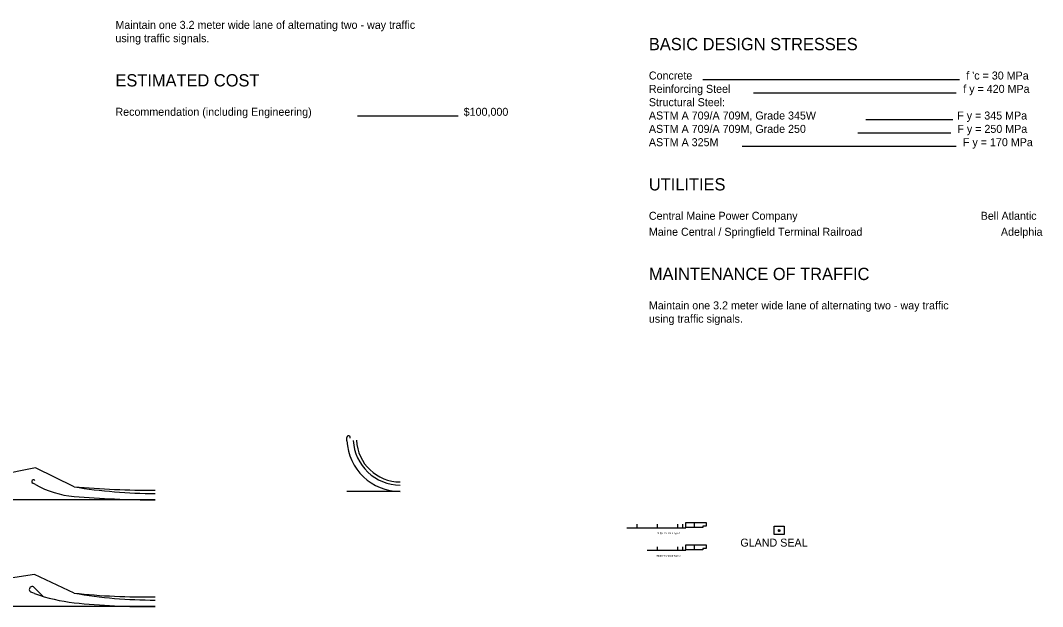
# Model space of a CAD drawing. Extents: x 604404 to 604584, y 419490 to 419604.
# Drawn here: x 604487.3 to 604583.1, y 419489.5 to 419544.5 of the extents above; entities that cross this region are included whole.
import ezdxf

# ---------------------------------------------------------------- set-up
doc = ezdxf.new("R2010")
doc.units = 0
for name, color, linetype in [('Level 17', 7, 'Continuous'), ('Level 18', 7, 'Continuous'), ('Level 19', 7, 'Continuous'), ('Level 20', 7, 'Continuous'), ('Level 21', 7, 'Continuous'), ('Level 27', 7, 'Continuous'), ('Level 28', 7, 'Continuous'), ('Level 50', 7, 'Continuous'), ('Level 51', 7, 'Continuous')]:
    doc.layers.add(name, color=color, linetype=linetype)

msp = doc.modelspace()

# ---------------------------------------------------------------- linework, layer by layer
at = {"layer": 'Level 17'}
for p, q in [((604488.722, 419502.516), (604473.719, 419499.516)), ((604492.337, 419500.741), (604488.722, 419502.516)), ((604550.478, 419496.919), (604550.478, 419497.394)), ((604550.478, 419494.82), (604550.478, 419495.295)), ((604488.638, 419492.516), (604468.638, 419489.516)), ((604492.34, 419490.771), (604488.638, 419492.516))]:
    msp.add_line(p, q, dxfattribs=at)
for points in [[(604551.278, 419496.919), (604549.678, 419496.919), (604549.678, 419497.394), (604551.578, 419497.394), (604551.578, 419497.049), (604551.278, 419497.049), (604551.278, 419496.919)], [(604551.278, 419494.82), (604549.678, 419494.82), (604549.678, 419495.295), (604551.578, 419495.295), (604551.578, 419494.95), (604551.278, 419494.95), (604551.278, 419494.82)]]:
    msp.add_lwpolyline(points, dxfattribs=at)
for centre, radius, start, end in [((604522.907, 419505.298), 4.4, 182.68063, 270.00009), ((604522.907, 419505.298), 4.1, 182.68063, 270.00009), ((604499.947, 419589.674), 89.258, 265.10911, 270), ((604499.947, 419546.759), 46.642, 260.60981, 270), ((604499.141, 419554.827), 64.416, 263.93933, 267.32786), ((604499.947, 419534.617), 44.5, 260.15738, 270), ((604499.141, 419554.827), 64.416, 267.32786, 270.71684)]:
    msp.add_arc(centre, radius, start, end, dxfattribs=at)
at = {"layer": 'Level 18'}
for p, q in [((604517.913, 419505.065), (604517.899, 419505.362)), ((604488.719, 419500.943), (604488.458, 419501.088)), ((604488.638, 419490.736), (604488.319, 419490.854)), ((604489.443, 419490.465), (604488.606, 419491.303))]:
    msp.add_line(p, q, dxfattribs=at)
for centre, radius, start, end in [((604518.061, 419505.37), 0.163, 336.2087, 182.6597), ((604522.907, 419505.298), 5, 182.68063, 270), ((604488.538, 419501.231), 0.163, 34.42209, 240.87309), ((604493.097, 419508.807), 9, 240.89401, 265.14953), ((604499.947, 419589.516), 90, 265.14894, 270), ((604488.413, 419491.11), 0.273, 44.93167, 249.75607), ((604493.965, 419505.184), 15.398, 249.7574, 263.93933), ((604499.141, 419553.927), 64.416, 263.93933, 267.32786), ((604499.141, 419553.927), 64.416, 267.32786, 270.71684)]:
    msp.add_arc(centre, radius, start, end, dxfattribs=at)
at = {"layer": 'Level 19'}
for p, q in [((604558.292, 419496.654), (604558.394, 419496.654)), ((604558.365, 419496.645), (604558.302, 419496.645)), ((604558.378, 419496.669), (604558.378, 419496.694)), ((604558.378, 419496.687), (604558.378, 419496.694)), ((604558.378, 419496.669), (604558.378, 419496.675)), ((604558.385, 419496.562), (604558.385, 419496.625)), ((604558.386, 419496.694), (604558.386, 419496.691)), ((604558.386, 419496.671), (604558.386, 419496.669)), ((604558.386, 419496.671), (604558.386, 419496.669)), ((604558.387, 419496.689), (604558.398, 419496.682)), ((604558.392, 419496.692), (604558.399, 419496.7)), ((604558.393, 419496.656), (604558.393, 419496.671)), ((604558.393, 419496.669), (604558.393, 419496.671)), ((604558.402, 419496.661), (604558.394, 419496.666)), ((604558.394, 419496.654), (604558.394, 419496.552)), ((604558.401, 419496.675), (604558.401, 419496.673)), ((604558.405, 419496.667), (604558.406, 419496.666)), ((604558.444, 419496.667), (604558.443, 419496.666)), ((604558.447, 419496.661), (604558.455, 419496.666)), ((604558.448, 419496.675), (604558.448, 419496.673)), ((604558.457, 419496.692), (604558.45, 419496.7)), ((604558.462, 419496.689), (604558.451, 419496.682)), ((604558.454, 419496.654), (604558.454, 419496.552)), ((604558.556, 419496.654), (604558.454, 419496.654)), ((604558.456, 419496.656), (604558.456, 419496.671)), ((604558.456, 419496.669), (604558.456, 419496.671)), ((604558.463, 419496.694), (604558.463, 419496.691)), ((604558.463, 419496.671), (604558.463, 419496.669)), ((604558.463, 419496.671), (604558.463, 419496.669)), ((604558.464, 419496.562), (604558.464, 419496.625)), ((604558.471, 419496.669), (604558.471, 419496.694)), ((604558.471, 419496.687), (604558.471, 419496.694)), ((604558.471, 419496.669), (604558.471, 419496.675)), ((604558.483, 419496.645), (604558.547, 419496.645))]:
    msp.add_line(p, q, dxfattribs=at)
for points in [[(604558.399, 419496.702), (604558.393, 419496.708), (604558.372, 419496.708), (604558.366, 419496.702), (604558.366, 419496.661), (604558.372, 419496.654), (604558.391, 419496.654)], [(604558.45, 419496.702), (604558.456, 419496.708), (604558.476, 419496.708), (604558.483, 419496.702), (604558.483, 419496.661), (604558.476, 419496.654), (604558.458, 419496.654)]]:
    msp.add_lwpolyline(points, dxfattribs=at)
for centre, radius, start, end in [((604558.302, 419496.654), 0.0095, 180, 270), ((604558.365, 419496.625), 0.0195, 0, 90), ((604558.382, 419496.694), 0.00422, 6.06579, 180), ((604558.382, 419496.694), 0.00422, 0, 180), ((604558.374, 419496.681), 0.00675, 300, 60), ((604558.382, 419496.669), 0.00422, 180, 0), ((604558.382, 419496.669), 0.00422, 180, 0), ((604558.394, 419496.562), 0.0095, 180, 270), ((604558.389, 419496.695), 0.00337, 186.07126, 315.00547), ((604558.388, 419496.691), 0.00169, 180, 236.30993), ((604558.389, 419496.671), 0.00337, 0, 180), ((604558.389, 419496.671), 0.00337, 0, 180), ((604558.391, 419496.656), 0.00169, 270, 0), ((604558.396, 419496.669), 0.00337, 180, 233.5525), ((604558.393, 419496.675), 0.00796, 0, 56.30993), ((604558.398, 419496.701), 0.00169, 315, 45), ((604558.405, 419496.673), 0.00435, 180, 211.60414), ((604558.414, 419496.678), 0.0145, 211.60414, 228.73675), ((604558.384, 419496.637), 0.0296, 31.29763, 53.5525), ((604558.384, 419496.637), 0.0364, 31.29763, 53.5525), ((604558.358, 419496.621), 0.06, 18.73675, 31.29763), ((604558.358, 419496.621), 0.0668, 18.73675, 31.29763), ((604558.409, 419496.625), 0.00868, 0.76049, 15.51312), ((604558.427, 419496.625), 0.0101, 180.76049, 205.08357), ((604558.424, 419496.623), 0.0061, 205.08357, 243.73675), ((604558.424, 419496.625), 0.00756, 243.73675, 269.84716), ((604558.409, 419496.625), 0.0155, 0.76049, 15.24409), ((604558.427, 419496.625), 0.00329, 180.76049, 205.08357), ((604558.421, 419496.625), 0.00329, 334.91643, 359.23951), ((604558.424, 419496.625), 0.00756, 270.15284, 296.26325), ((604558.44, 419496.625), 0.0155, 164.75591, 179.23951), ((604558.491, 419496.621), 0.0668, 148.70237, 161.26325), ((604558.425, 419496.623), 0.0061, 296.26325, 334.91643), ((604558.421, 419496.625), 0.0101, 334.91643, 359.23951), ((604558.44, 419496.625), 0.00868, 164.48688, 179.23951), ((604558.465, 419496.637), 0.0364, 126.4475, 148.70237), ((604558.491, 419496.621), 0.06, 148.70237, 161.26325), ((604558.465, 419496.637), 0.0296, 126.4475, 148.70237), ((604558.435, 419496.678), 0.0145, 311.26325, 328.39586), ((604558.443, 419496.673), 0.00435, 328.39586, 0), ((604558.456, 419496.675), 0.00796, 123.69007, 180), ((604558.451, 419496.701), 0.00169, 135, 225), ((604558.454, 419496.562), 0.0095, 270, 0), ((604558.453, 419496.669), 0.00337, 306.4475, 360), ((604558.46, 419496.671), 0.00337, 0, 180), ((604558.46, 419496.671), 0.00337, 0, 180), ((604558.458, 419496.656), 0.00169, 180, 270), ((604558.46, 419496.695), 0.00337, 224.99453, 353.92874), ((604558.461, 419496.691), 0.00169, 303.69007, 360), ((604558.467, 419496.694), 0.00422, 360, 173.93421), ((604558.467, 419496.694), 0.00422, 0, 180), ((604558.467, 419496.669), 0.00422, 180, 0), ((604558.467, 419496.669), 0.00422, 180, 0), ((604558.483, 419496.625), 0.0195, 90, 180), ((604558.475, 419496.681), 0.00675, 120, 240), ((604558.547, 419496.654), 0.0095, 270, 0)]:
    msp.add_arc(centre, radius, start, end, dxfattribs=at)
for centre, major_axis, ratio, start_param, end_param in [((604558.294, 419496.561), (0, 0.248), 0.515887, 4.983144, 5.039407), ((604558.294, 419496.561), (0, 0.255), 0.528815, 4.982856, 5.039407), ((604558.555, 419496.561), (0, -0.255), 0.528815, 4.385371, 4.441922), ((604558.555, 419496.561), (0, -0.248), 0.515887, 4.385371, 4.441634)]:
    msp.add_ellipse(centre, major_axis=major_axis, ratio=ratio, start_param=start_param, end_param=end_param, dxfattribs=at)
at = {"layer": 'Level 20'}
for p, q in [((604551.26, 419538.924), (604575.335, 419538.924)), ((604556.034, 419537.674), (604575.026, 419537.674)), ((604518.907, 419535.524), (604528.351, 419535.524)), ((604566.543, 419535.174), (604574.717, 419535.174)), ((604565.787, 419533.924), (604574.511, 419533.924)), ((604554.969, 419532.674), (604575.026, 419532.674))]:
    msp.add_line(p, q, dxfattribs=at)
at = {"layer": 'Level 21'}
for p, q in [((604545.041, 419497.194), (604545.141, 419497.194)), ((604545.091, 419497.194), (604545.091, 419496.894)), ((604546.946, 419497.194), (604547.046, 419497.194)), ((604546.996, 419497.194), (604546.996, 419496.894)), ((604548.851, 419497.194), (604548.951, 419497.194)), ((604548.901, 419497.194), (604548.901, 419496.894)), ((604549.327, 419497.194), (604549.427, 419497.194)), ((604549.377, 419497.194), (604549.377, 419496.894)), ((604544.139, 419496.894), (604549.678, 419496.894)), ((604545.041, 419497.044), (604545.141, 419497.044)), ((604546.946, 419497.044), (604547.046, 419497.044)), ((604548.851, 419497.044), (604548.951, 419497.044)), ((604549.327, 419497.044), (604549.427, 419497.044)), ((604546.044, 419494.795), (604549.678, 419494.795)), ((604546.946, 419495.095), (604547.046, 419495.095)), ((604546.946, 419494.945), (604547.046, 419494.945)), ((604546.996, 419495.095), (604546.996, 419494.795)), ((604548.851, 419495.095), (604548.951, 419495.095)), ((604548.851, 419494.945), (604548.951, 419494.945)), ((604548.901, 419495.095), (604548.901, 419494.795)), ((604549.327, 419495.095), (604549.427, 419495.095)), ((604549.327, 419494.945), (604549.427, 419494.945)), ((604549.377, 419495.095), (604549.377, 419494.795))]:
    msp.add_line(p, q, dxfattribs=at)
at = {"layer": 'Level 27'}
msp.add_lwpolyline([(604558.89, 419496.256), (604557.959, 419496.256), (604557.959, 419497.053), (604558.89, 419497.053)], close=True, dxfattribs=at)
at = {"layer": 'Level 28'}
for p, q in [((604558.393, 419496.708), (604558.456, 419496.708)), ((604558.424, 419496.507), (604558.424, 419496.708))]:
    msp.add_line(p, q, dxfattribs=at)
at = {"layer": 'Level 50'}
for p, q in [((604522.907, 419500.298), (604517.913, 419500.298)), ((604499.947, 419499.516), (604473.719, 419499.516)), ((604499.947, 419489.516), (604468.638, 419489.516))]:
    msp.add_line(p, q, dxfattribs=at)
at = {"layer": 'Level 51'}
for p, q in [((604558.378, 419496.694), (604558.378, 419496.687)), ((604558.378, 419496.675), (604558.378, 419496.669)), ((604558.386, 419496.691), (604558.386, 419496.694)), ((604558.386, 419496.669), (604558.386, 419496.671)), ((604558.398, 419496.682), (604558.387, 419496.689)), ((604558.393, 419496.671), (604558.393, 419496.669)), ((604558.394, 419496.666), (604558.402, 419496.661)), ((604558.401, 419496.673), (604558.401, 419496.675)), ((604558.406, 419496.666), (604558.405, 419496.667)), ((604558.444, 419496.667), (604558.443, 419496.666)), ((604558.447, 419496.661), (604558.455, 419496.666)), ((604558.448, 419496.675), (604558.448, 419496.673)), ((604558.462, 419496.689), (604558.451, 419496.682)), ((604558.456, 419496.669), (604558.456, 419496.671)), ((604558.463, 419496.694), (604558.463, 419496.691)), ((604558.463, 419496.671), (604558.463, 419496.669)), ((604558.471, 419496.687), (604558.471, 419496.694)), ((604558.471, 419496.669), (604558.471, 419496.675))]:
    msp.add_line(p, q, dxfattribs=at)
for centre, radius, start, end in [((604558.382, 419496.694), 0.00422, 0.0004, 180), ((604558.374, 419496.681), 0.00675, 300, 60), ((604558.382, 419496.669), 0.00422, 180.00012, 0), ((604558.389, 419496.671), 0.00337, 360, 179.99989), ((604558.396, 419496.669), 0.00337, 180.00045, 233.5525), ((604558.393, 419496.675), 0.00796, 0, 56.30993), ((604558.405, 419496.673), 0.00435, 180, 211.58373), ((604558.414, 419496.678), 0.0145, 211.60414, 228.73633), ((604558.384, 419496.637), 0.0296, 31.29763, 53.55248), ((604558.384, 419496.637), 0.0364, 31.29763, 52.34679), ((604558.358, 419496.621), 0.06, 18.73675, 31.2919), ((604558.358, 419496.621), 0.0668, 18.73675, 31.29763), ((604558.409, 419496.625), 0.00868, 0.76049, 15.51309), ((604558.427, 419496.625), 0.0101, 180.7605, 205.08357), ((604558.424, 419496.623), 0.0061, 205.08379, 243.73675), ((604558.424, 419496.625), 0.00756, 243.73675, 269.84716), ((604558.424, 419496.625), 0.00756, 270.15284, 296.26325), ((604558.491, 419496.621), 0.0668, 148.70237, 161.26325), ((604558.425, 419496.623), 0.0061, 296.26325, 334.91643), ((604558.421, 419496.625), 0.0101, 334.91643, 359.23951), ((604558.44, 419496.625), 0.00868, 164.48688, 179.23951), ((604558.465, 419496.637), 0.0364, 127.65321, 148.70237), ((604558.491, 419496.621), 0.06, 148.70237, 161.26325), ((604558.465, 419496.637), 0.0296, 126.4475, 148.70237), ((604558.435, 419496.678), 0.0145, 311.26325, 328.39586), ((604558.443, 419496.673), 0.00435, 328.39586, 0), ((604558.456, 419496.675), 0.00796, 123.69007, 180), ((604558.453, 419496.669), 0.00337, 306.4475, 360), ((604558.46, 419496.671), 0.00337, 0, 180), ((604558.467, 419496.694), 0.00422, 0, 180), ((604558.467, 419496.669), 0.00422, 180, 0), ((604558.475, 419496.681), 0.00675, 120, 240)]:
    msp.add_arc(centre, radius, start, end, dxfattribs=at)
for centre, major_axis, ratio, start_param, end_param in [((604558.294, 419496.561), (0, 0.248), 0.515887, 4.983144, 5.039407), ((604558.294, 419496.561), (0, 0.255), 0.528815, 4.982856, 5.039407), ((604558.555, 419496.561), (0, -0.255), 0.528815, 4.385371, 4.441922), ((604558.555, 419496.561), (0, -0.248), 0.515887, 4.385371, 4.441634)]:
    msp.add_ellipse(centre, major_axis=major_axis, ratio=ratio, start_param=start_param, end_param=end_param, dxfattribs=at)

# ---------------------------------------------------------------- texts
at = {"layer": 'Level 20'}
for s, height, p in [('Maintain one 3.2 meter wide lane of alternating two - way traffic', 0.75, (604496.214, 419543.674)), ('using traffic signals.', 0.75, (604496.214, 419542.424)), ('BASIC DESIGN STRESSES', 1.1499, (604546.214, 419541.674)), ('ESTIMATED COST', 1.1499, (604496.214, 419538.274)), ('Concrete', 0.75, (604546.214, 419538.924)), ("f 'c = 30 MPa", 0.75, (604575.963, 419538.924)), ('Reinforcing Steel', 0.75, (604546.214, 419537.674)), ('f y = 420 MPa', 0.75, (604575.681, 419537.674)), ('Structural Steel:', 0.75, (604546.214, 419536.424)), ('Recommendation (including Engineering)', 0.75, (604496.214, 419535.524)), ('$100,000', 0.75, (604528.857, 419535.524)), ('ASTM A 709/A 709M, Grade 345W', 0.75, (604546.214, 419535.174)), ('F y = 345 MPa', 0.75, (604575.115, 419535.174)), ('ASTM A 709/A 709M, Grade 250', 0.75, (604546.214, 419533.924)), ('F y = 250 MPa', 0.75, (604575.128, 419533.924)), ('ASTM A 325M', 0.75, (604546.214, 419532.674)), ('F y = 170 MPa', 0.75, (604575.65, 419532.674)), ('UTILITIES', 1.1499, (604546.214, 419528.524)), ('Central Maine Power Company', 0.75, (604546.214, 419525.774)), ('Bell Atlantic', 0.75, (604577.314, 419525.774)), ('Maine Central / Springfield Terminal Railroad', 0.75, (604546.214, 419524.274)), ('Adelphia', 0.75, (604579.209, 419524.274)), ('MAINTENANCE OF TRAFFIC', 1.1499, (604546.214, 419520.124)), ('Maintain one 3.2 meter wide lane of alternating two - way traffic', 0.75, (604546.214, 419517.374)), ('using traffic signals.', 0.75, (604546.214, 419516.124))]:
    msp.add_text(s, height=height, dxfattribs=at).set_placement(p)
at = {"layer": 'Level 27'}
for s, height, p in [('Bridge Transition Type 1', 0.15, (604546.92, 419496.333)), ('GLAND SEAL', 0.75, (604554.79, 419495.131)), ('Bridge Transition Type 2', 0.15, (604546.92, 419494.196))]:
    msp.add_text(s, height=height, dxfattribs=at).set_placement(p)

doc.saveas('drawing.dxf')
